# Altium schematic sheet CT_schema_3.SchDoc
size 293 x 134 mm
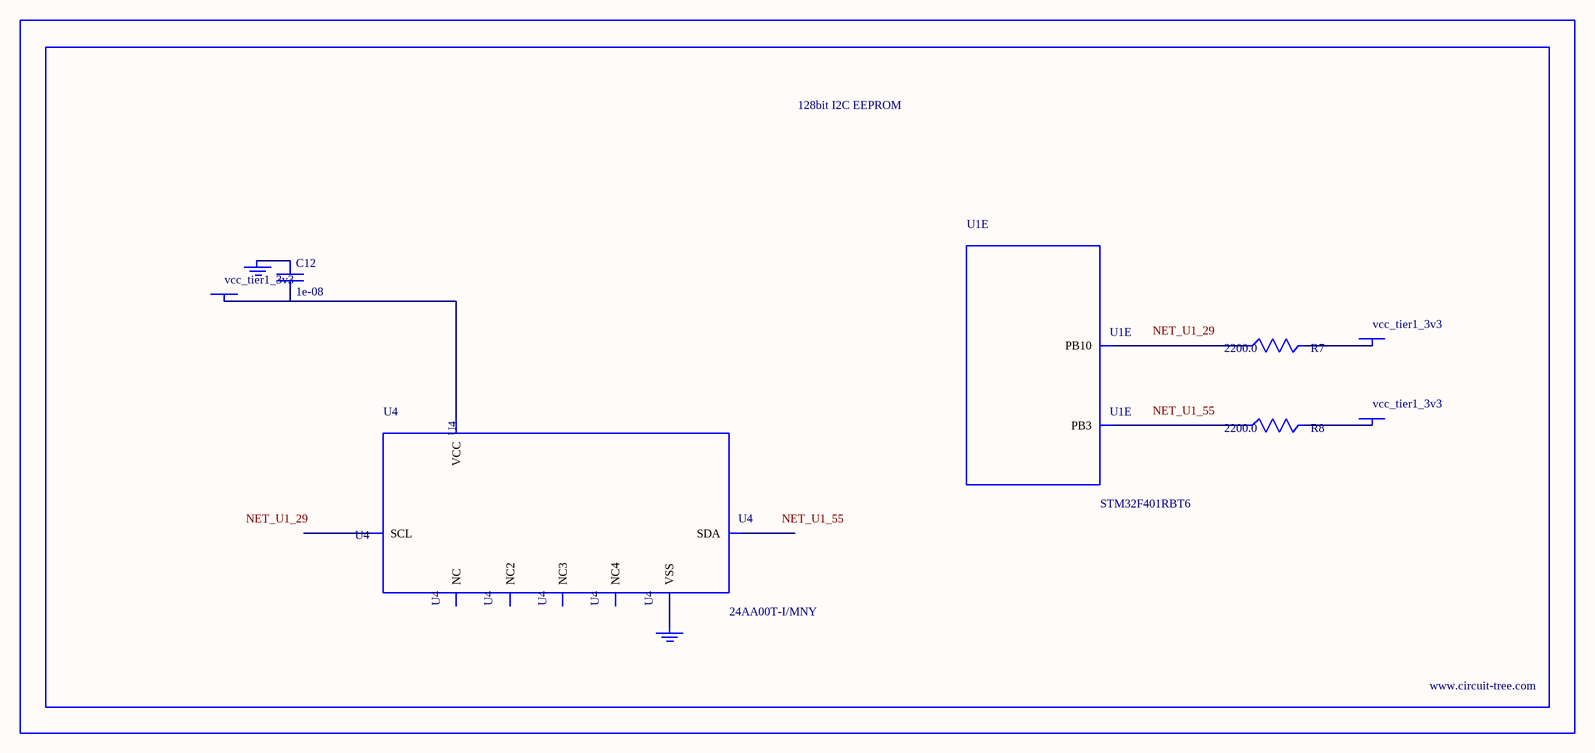
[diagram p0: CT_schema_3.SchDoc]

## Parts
BORDER2  (no value)
C12  1e-08  [C0402]
GND_INSTANCE_2_0  (no value)
GND_INSTANCE_2_1  (no value)
POWER_INSTANCE_2_0  vcc_tier1_3v3
POWER_INSTANCE_2_1  vcc_tier1_3v3
POWER_INSTANCE_2_2  vcc_tier1_3v3
R7  2200.0  [R0603]
R8  2200.0  [R0603]
U1  STM32F401RBT6  [LQFP64]  (part E of 7)
U4  24AA00T-I/MNY  [TDFN-8/6MM]

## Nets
NetC12_1: C12.1 GND_INSTANCE_2_0.0(GND)
NetC12_2: C12.2 POWER_INSTANCE_2_0.0(PWR) U4.8(VCC)
NetGND_INSTANCE_2_1_0: GND_INSTANCE_2_1.0(GND) U4.4(VSS)
NetPOWER_INSTANCE_2_1_0: POWER_INSTANCE_2_1.0(PWR) R7.2
NetPOWER_INSTANCE_2_2_0: POWER_INSTANCE_2_2.0(PWR) R8.2
NetR7_1: R7.1 U1.29(PB10)
NetR8_1: R8.1 U1.55(PB3)

Not connected (* = marked no-connect by the designer): U4 1(NC) 2(NC2) 3(NC3) 5(SDA) 6(SCL) 7(NC4)

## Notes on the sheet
- Labels drawn without touching a wire or pin: NET_U1_29, NET_U1_55

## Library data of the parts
BORDER2 = BORDER_PAGE2
C12 = C0402C103K3RAC
GND_INSTANCE_2_0 GND_INSTANCE_2_1 = GND
POWER_INSTANCE_2_0-POWER_INSTANCE_2_2 = PWR
R7 R8 = RC0603JR-072K2L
